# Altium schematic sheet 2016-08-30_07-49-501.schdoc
size 331 x 127 mm; SheetNumber: 1; SheetTotal: 1
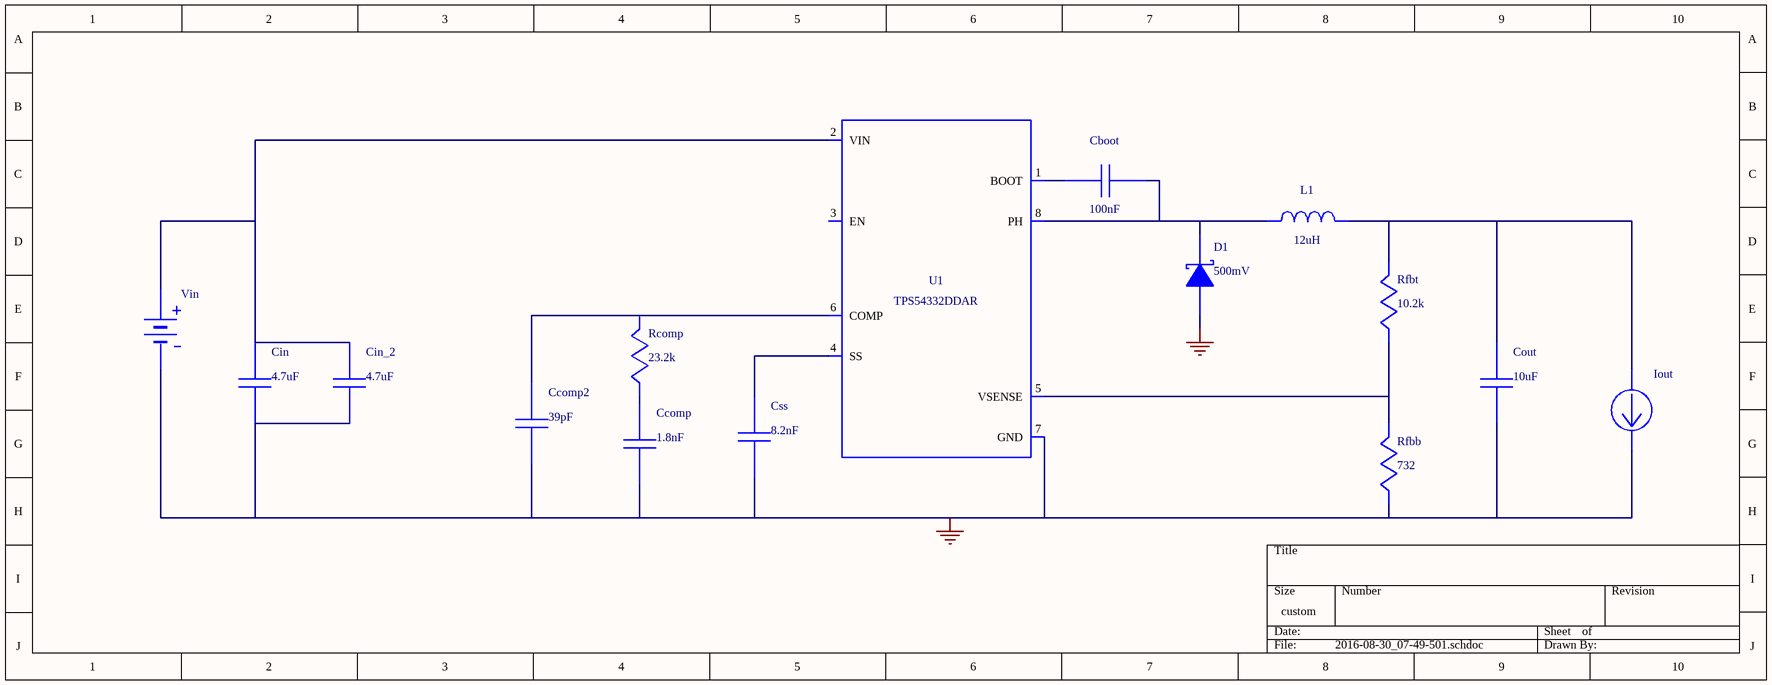
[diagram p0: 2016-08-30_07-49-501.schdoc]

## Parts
Cboot  value 100nF  (hidden comment: GRM155R61A104KA01D)
Ccomp  value 1.8nF  (hidden comment: GRM033R71A182KA01D)
Ccomp2  value 39pF  (hidden comment: CC0805JRNPO9BN390)
Cin  value 4.7uF  (hidden comment: GRM32ER71H475KA88L)
Cin_2  value 4.7uF  (hidden comment: GRM32ER71H475KA88L)
Cout  value 10uF  (hidden comment: GRM31CR71E106KA12L)
Css  value 8.2nF  (hidden comment: GRM033R61A822KA01D)
D1  value 500mV  (hidden comment: B240A-13-F)
Iout  WB_CURRENT_LOAD  (value not drawn)
L1  value 12uH  (hidden comment: SRR1206-120ML)
Rcomp  value 23.2k  (hidden comment: CRCW040223K2FKED)
Rfbb  value 732  (hidden comment: CRCW0402732RFKED)
Rfbt  value 10.2k  (hidden comment: CRCW040210K2FKED)
U1  TPS54332DDAR
Vin  WB_BATTERY  (value not drawn)

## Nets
0: Ccomp.2 Ccomp2.2 Cin.2 Cin_2.2 Cout.2 Css.2 D1.2(A) Iout.2(-) Rfbb.2 U1.7(GND) U1.9(ETPAD) Vin.2(-)
NetCboot_1: Cboot.1 U1.1(BOOT)
NetCboot_2: Cboot.2 D1.1(K) L1.2 U1.8(PH)
NetCcomp2_1: Ccomp2.1 Rcomp.1 U1.6(COMP)
NetCcomp_1: Ccomp.1 Rcomp.2
NetCin_1: Cin.1 Cin_2.1 U1.2(VIN) Vin.1(+)
NetCout_1: Cout.1 Iout.1(+) L1.1 Rfbt.1
NetCss_1: Css.1 U1.4(SS)
NetRfbb_1: Rfbb.1 Rfbt.2 U1.5(VSENSE)

Not connected (* = marked no-connect by the designer): U1 3(EN)

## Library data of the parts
Cboot = GRM155R61A104KA01D: GRM155R61A104KA0; Manufacturer Name: MuRata
Ccomp = GRM033R71A182KA01D: GRM033R71A182KA0; Manufacturer Name: MuRata
Ccomp2 = CC0805JRNPO9BN390: CC0805JRNPO9BN39; Manufacturer Name: Yageo America
Cin Cin_2 = GRM32ER71H475KA88L: GRM32ER71H475KA8; Manufacturer Name: MuRata
Cout = GRM31CR71E106KA12L: GRM31CR71E106KA1; Manufacturer Name: MuRata
Css = GRM033R61A822KA01D: GRM033R61A822KA0; Manufacturer Name: MuRata
D1 = B240A-13-F: Manufacturer Name: Diodes Inc.
L1 = SRR1206-120ML: Manufacturer Name: Bourns
Rcomp = CRCW040223K2FKED: Manufacturer Name: Vishay-Dale
Rfbb = CRCW0402732RFKED: Manufacturer Name: Vishay-Dale
Rfbt = CRCW040210K2FKED: Manufacturer Name: Vishay-Dale
U1 = TPS54332DDAR: Manufacturer Name: Texas Instruments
